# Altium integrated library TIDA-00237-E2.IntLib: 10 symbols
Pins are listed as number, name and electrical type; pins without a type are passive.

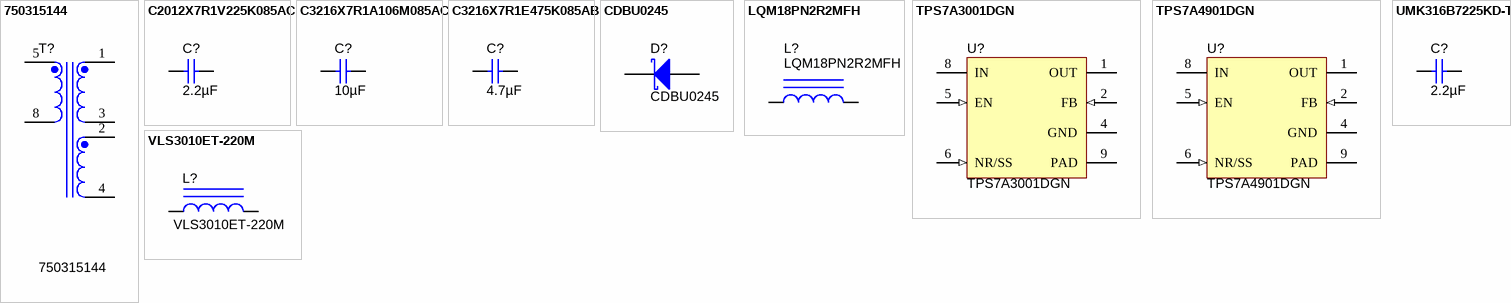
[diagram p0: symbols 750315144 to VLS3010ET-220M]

## 750315144
designator T?
Transformer, 22 uH, SMT; Manufacturer: Wurth Elektronik eiSos; SymbolCreator: Altium; DCR_Ohm: 0.141; Value: 22 uH; U/M: EA
footprint WURTH_750315144
pins: 1, 2, 3, 4, 5, 8

## C2012X7R1V225K085AC
designator C?  ValueDisplayed: 2.2µF  (hidden comment: C2012X7R1V225K085AC)
CAP, CERM, 2.2 µF, 35 V, +/- 10%, X7R, 0805; Manufacturer: TDK; Polarized: N; CompType: Capacitor; Value: 2.2uF; U/M: EA; Cap_F: 0.0000022; Tolerance_%: 10; Value1: Unknown; VDC_V: 35; Value2: 35V; TaMin_C: -55; TaMax_C: 125; Cap_Case: 0805
signal-integrity model Cap
simulation model Cap
footprint 0805_HV_033 (Low profile 0805 package)
pins: 1, 2

## C3216X7R1A106M085AC
designator C?  ValueDisplayed: 10µF  (hidden comment: C3216X7R1A106M085AC)
CAP, CERM, 10 µF, 10 V, +/- 20%, X7R, 1206; Manufacturer: TDK; Polarized: N; CompType: Capacitor; Value: 10uF; U/M: EA; Cap_F: 0.00001; Tolerance_%: 20; ESR_ohm: 0.0046; Value1: 0.0046 ohm; VDC_V: 10; Value2: 10V; TaMin_C: -55; TaMax_C: 125; Cap_Case: 1206
signal-integrity model Cap
simulation model Cap
footprint 1206_033 (Low profile 1206)
pins: 1, 2

## C3216X7R1E475K085AB
designator C?  ValueDisplayed: 4.7µF  (hidden comment: C3216X7R1E475K085AB)
CAP, CERM, 4.7 µF, 25 V, +/- 10%, X7R, 1206; Manufacturer: TDK; Polarized: N; CompType: Capacitor; Value: 4.7uF; U/M: EA; Cap_F: 0.0000047; Tolerance_%: 10; ESR_ohm: 0.0063; Value1: 0.0063 ohm; VDC_V: 25; Value2: 25V; TaMin_C: -55; TaMax_C: 125; Cap_Case: 1206
signal-integrity model Cap
simulation model Cap
footprint 1206_033 (Low profile 1206)
pins: 1, 2

## CDBU0245
designator D?
Diode, Schottky, 45 V, 0.2 A, SOD-523F; Manufacturer: Comchip Technology; Value: 45V; U/M: EA; Value1: 0.2A; Io_A: 0.2; Vr_V: 45; TJmax_C: 125
signal-integrity model Diode
footprint SOD-523F
pins: 1 K, 2 A

## LQM18PN2R2MFH
designator L?
Inductor, Ferrite, 2.2 µH, 0.35 A, 0.38 ohm, SMD; Manufacturer: MuRata; Value: 2.2uH; Imax_A: 0.35; DCR_ohm: 0.38; Value2: 0.35A; Ind_H: 2.2E-6; ValueDisplayed: 2.2µH; Irms: 0.9A @ 40C rise; Isat: 0.35A @ 30% inductance drop
signal-integrity model Inductor
simulation model Inductor
footprint 0603
pins: 1, 2

## TPS7A3001DGN
designator U?
-36V, -200mA, Ultralow-Noise, High PSRR, Adjustable -1.18 to -33 V Output, Negative Linear Regulator, 8-pin MSOP (DGN), -40 to 125 degC, Green (RoHS & no Sb/Br); Manufacturer: Texas Instruments; Alternate Manufacturer: None; Alternate PartNumber: Equivalent; Accuracy(%): 1.5; Iout(Max)(A): 0.2; Iq(Typ)(mA): 0.05; SubFamily: Single Channel LDO; Vdo(Typ)(mV): 216; Vin(Max)(V): -36; Vin(Min)(V): -3
footprint DGN0008D_N
footprint DGN0008D_L (SOIC, 8-Leads, Body 3x3mm, Pitch 0.65mm, Thermal Pad 1.76x1.425mm, IPC High Density)
footprint DGN0008D_M (SOIC, 8-Leads, Body 3x3mm, Pitch 0.65mm, Thermal Pad 1.76x1.425mm, IPC Low Density)
pins: 1 OUT (power) "Regulator output. A capacitor>=2.2 uF must be tied from this pin to ground to assure stability.", 2 FB (in) "This pin is the input to the control-loop error amplifier. It is used to set the output voltage of the device.", 3 NC hidden "Not internally connected. This pin must either be left open or tied to GND.", 4 GND (power) "Ground", 5 EN (in) "This pin turns the regulator on or off. If VEN>= V+EN_HI or VEN=< V-EN_HI, the regulator is enabled. If V+EN_LO>=VEN>= V-EN_LO, the regulator is disabled. The EN pin can be connected to IN, if not used. |VEN|=< |VIN|.", 6 NR/SS (in) "Noise reduction pin. Connecting an external capacitor to this pin bypasses noise generated by the internal bandgap. This capacitor allows RMS noise to be reduced to very low levels and also controls the soft-start function.", 7 DNC hidden "DO NOT CONNECT. Do not route this pin to any electrical net, not even GND or IN.", 8 IN (power) "Input supply", 9 PAD "Must either be left open or tied to GND. Solder to printed circuit board (PCB) plane to enhance thermal performance"

## TPS7A4901DGN
designator U?
+36V, +150mA, Ultralow-Noise, Positive LINEAR REGULATOR, DGN0008D; Manufacturer: Texas Instruments; SymbolCreator: a0411947; CompType: IC; U/M: EA
footprint DGN0008D_N
footprint DGN0008D_M
footprint DGN0008D_L
pins: 1 OUT (power), 2 FB (in), 3 NC hidden, 4 GND (power), 5 EN (in), 6 NR/SS (in), 7 DNC hidden, 8 IN (power), 9 PAD (power)

## UMK316B7225KD-T
designator C?  ValueDisplayed: 2.2µF  (hidden comment: UMK316B7225KD-T)
CAP, CERM, 2.2 µF, 50 V, +/- 10%, X7R, 1206; Manufacturer: Taiyo Yuden; Polarized: N; CompType: Capacitor; Value: 2.2uF; U/M: EA; Cap_F: 0.0000022; Tolerance_%: 10; Value1: Unknown; VDC_V: 50; Value2: 50V; TaMin_C: -55; TaMax_C: 125; Cap_Case: 1206
signal-integrity model Cap
simulation model Cap
footprint 1206_033 (Low profile 1206)
pins: 1, 2

## VLS3010ET-220M
designator L?
Inductor, Shielded, Ferrite, 22 µH, 0.38 A, 0.9 ohm, SMD; Manufacturer: TDK; Value: 22uH; Ind_H: 22.0E-6; ValueDisplayed: 22µH; Imax_A: 0.38; Irms: 0.6A @ 40C rise; Isat: 0.38A @ 30% inductance drop; DCR_ohm: 0.9; Value1: 0.9 ohm; Value2: 0.38A
signal-integrity model Inductor
simulation model Inductor
footprint VLS3010
pins: 1, 2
